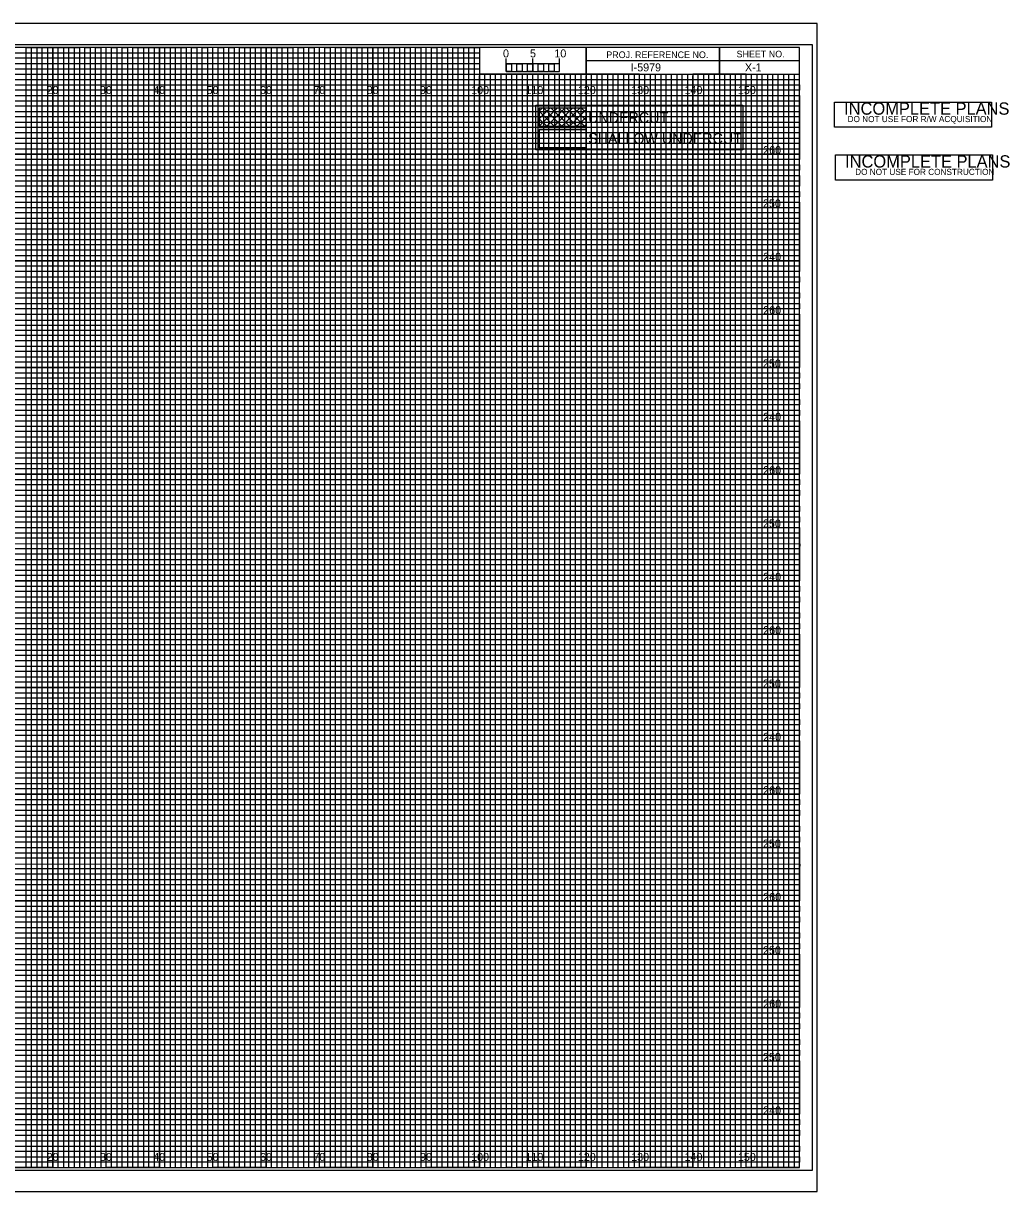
# Model space of a CAD drawing. Extents: x -13 to 359, y -5 to 2854.
# Drawn here: x 174.5 to 359.4, y -4.5 to 214.5 of the extents above; entities that cross this region are included whole.
import ezdxf

# ---------------------------------------------------------------- set-up
doc = ezdxf.new("R2010")
doc.units = 0
for name, color, linetype in [('Exist CMT Pavement', 7, 'Continuous'), ('Exist Cross Section Cell', 7, 'Continuous'), ('Exist XS Ground Line', 7, 'Continuous'), ('Prop CMT Conc Surface', 7, 'Continuous'), ('Prop CMT Concrete Structures', 7, 'Continuous'), ('Prop CMT DNC', 7, 'Continuous'), ('Prop CMT Guardrail Graphics', 7, 'Continuous'), ('Prop CMT Pvmt Course 1', 7, 'Continuous'), ('Prop CMT Pvmt Course 1 CG', 7, 'Continuous'), ('Prop CMT Pvmt Course 1 Wedge', 7, 'Continuous'), ('Prop CMT Pvmt Course 2', 7, 'Continuous'), ('Prop CMT Pvmt Course 2 Wedge', 7, 'Continuous'), ('Prop CMT Pvmt Surface', 7, 'Continuous'), ('Prop CMT Shear Line', 7, 'Continuous'), ('Prop CMT Shld Paved Course 1', 7, 'Continuous'), ('Prop CMT Shld Paved Course 2', 7, 'Continuous'), ('Prop CMT Shld Paved Course 3', 7, 'Continuous'), ('Prop CMT Slope Grass', 7, 'Continuous'), ('Prop CMT Subgrade Earthwork', 7, 'Continuous'), ('Scratch_Level_0', 7, 'Continuous')]:
    doc.layers.add(name, color=color, linetype=linetype)

msp = doc.modelspace()

# ---------------------------------------------------------------- linework, layer by layer
at = {"layer": 'Exist XS Ground Line'}
for p, q in [((190, 210), (180, 210)), ((180, 210), (180, 0)), ((190, 0), (190, 210)), ((210, 210), (200, 210)), ((200, 210), (200, 0)), ((210, 0), (210, 210)), ((230, 210), (220, 210)), ((220, 210), (220, 0)), ((230, 0), (230, 210)), ((250, 210), (240, 210)), ((240, 210), (240, 0)), ((250, 0), (250, 210)), ((260, 210), (260, 0)), ((270, 0), (270, 205)), ((290, 205), (280, 205)), ((280, 205), (280, 0)), ((290, 0), (290, 205)), ((310, 205), (300, 205)), ((300, 205), (300, 0)), ((310, 0), (310, 205)), ((180, 0), (170, 0)), ((200, 0), (190, 0)), ((220, 0), (210, 0)), ((240, 0), (230, 0)), ((260, 0), (250, 0)), ((280, 0), (270, 0)), ((300, 0), (290, 0)), ((320, 0), (310, 0)), ((320, 0), (320, 0))]:
    msp.add_line(p, q, dxfattribs=at)
for points in [[(0, 200), (320, 200), (320, 190), (0, 190)], [(0, 180), (320, 180), (320, 170), (0, 170)], [(0, 160), (320, 160), (320, 150), (0, 150)], [(0, 140), (320, 140), (320, 130), (0, 130)], [(0, 120), (320, 120), (320, 110), (0, 110)], [(0, 100), (320, 100), (320, 90), (0, 90)], [(0, 80), (320, 80), (320, 70), (0, 70)], [(0, 60), (320, 60), (320, 50), (0, 50)], [(0, 40), (320, 40), (320, 30), (0, 30)], [(0, 20), (320, 20), (320, 10), (0, 10)]]:
    msp.add_lwpolyline(points, dxfattribs=at)
at = {"layer": 'Prop CMT Conc Surface'}
for p, q in [((265, 205.49), (265, 207.9)), ((265, 206.9), (265, 207.9)), ((270, 205.49), (270, 207.9)), ((275, 205.49), (275, 207.9)), ((275, 206.9), (275, 207.9))]:
    msp.add_line(p, q, dxfattribs=at)
for points in [[(275, 206.9), (265, 206.9), (265, 205.49), (275, 205.49)], [(265, 206.9), (266, 206.9), (266, 205.49), (265, 205.49)], [(267, 206.9), (268, 206.9), (268, 205.49), (267, 205.49)], [(269, 206.9), (270, 206.9), (270, 205.49), (269, 205.49)], [(271, 206.9), (272, 206.9), (272, 205.49), (271, 205.49)], [(273, 206.9), (274, 206.9), (274, 205.49), (273, 205.49)]]:
    msp.add_lwpolyline(points, close=True, dxfattribs=at)
at = {"layer": 'Prop CMT Concrete Structures'}
for p, q in [((305, 210), (305, 205)), ((305, 205), (305, 210)), ((280, 207.5), (280, 205)), ((320, 207.49), (280, 207.49)), ((280, 205), (320, 205))]:
    msp.add_line(p, q, dxfattribs=at)
for points in [[(320, 210), (0, 210), (0, 0), (320, 0)], [(280, 210), (260, 210), (260, 205.03), (280, 205.03)], [(320, 210), (280, 210), (280, 205), (320, 205)]]:
    msp.add_lwpolyline(points, close=True, dxfattribs=at)
at = {"layer": 'Prop CMT DNC'}
for p, q in [((323.3, 214.5), (-13.4, 214.5)), ((-13.4, -4.5), (323.3, -4.5))]:
    msp.add_line(p, q, dxfattribs=at)
at = {"layer": 'Prop CMT Guardrail Graphics'}
msp.add_lwpolyline([(270.59, 199.19), (309.38, 199.19), (309.38, 190.78), (270.59, 190.78)], close=True, dxfattribs=at)
at = {"layer": 'Prop CMT Pvmt Course 1'}
for p, q in [((0, 209), (260, 209)), ((260, 209), (260, 207.98)), ((260, 207.98), (0, 207.98)), ((0, 207), (260, 207)), ((260, 205.89), (0, 205.89)), ((260, 207), (260, 205.89)), ((0, 204), (320, 204))]:
    msp.add_line(p, q, dxfattribs=at)
for points in [[(0, 203), (270, 203), (320, 203), (320, 202), (0, 202)], [(0, 201), (320, 201), (320, 199), (0, 199)], [(0, 198), (320, 198), (320, 197), (0, 196.98)], [(0, 196), (320, 196), (320, 194), (0, 194)], [(0, 193), (320, 193), (320, 192), (0, 192)], [(0, 191), (320, 191), (320, 189), (0, 189)], [(0, 188), (320, 188), (320, 187), (0, 187)], [(0, 186), (320, 186), (320, 184), (0, 184)], [(0, 183), (320, 183), (320, 182), (0, 182)], [(0, 181), (320, 181), (320, 179), (0, 179)], [(0, 178), (320, 178), (320, 177), (0, 177)], [(0, 176), (320, 176), (320, 173.95), (320, 173), (320, 172), (0, 172)], [(0, 174), (320, 174), (320, 173), (0, 173)], [(0, 171), (320, 171), (320, 169), (0, 169.03)], [(0, 169.03), (320, 169), (320, 168), (0, 168)], [(0, 167), (320, 167), (320, 166), (0, 166)], [(0, 164), (320, 164), (320, 163), (0, 163)], [(0, 162), (320, 162), (320, 161), (0, 161)], [(-0.07, 158.89), (320, 158.89), (320, 157.88), (-0.07, 157.88)], [(0, 157), (320, 157), (320, 156), (0, 156)], [(0, 154), (320, 154), (320, 153), (0, 153)], [(0, 152), (320, 152), (320, 151), (0, 151)], [(0, 149), (320, 149), (320, 148), (0, 148)], [(0, 147), (320, 147), (320, 146), (0, 146)], [(0, 144), (320, 144), (320, 143), (0, 143)], [(0, 142), (320, 142), (320, 141), (0, 141)], [(0, 139), (320, 139), (319.99, 137.98), (0, 138)], [(0, 137), (320, 137), (320, 136), (0, 136)], [(0, 134), (320, 134), (320, 133), (0, 133)], [(0, 132), (320, 132), (320, 131), (0, 131)], [(0, 129), (320, 129), (320, 128), (0, 128)], [(0, 127), (320, 127), (320, 126), (0, 126)], [(0, 124), (320, 124), (320, 123), (0, 123)], [(0, 122), (320, 122), (320, 121), (0, 121)], [(0, 119), (320, 119), (320, 118), (0, 118)], [(0, 116.99), (320.07, 116.91), (320, 116), (0, 116)], [(0, 114), (320, 114), (320, 113), (0, 113)], [(0, 112), (320, 112), (320, 111), (0, 111)], [(0, 109), (320, 109), (320, 108), (0, 108)], [(0, 107), (320, 107), (320, 106), (0, 106)], [(0, 104), (320, 104), (320, 103), (0, 103)], [(0, 102), (320, 102), (320, 101), (0, 101)], [(0, 99), (320, 99), (320, 98), (0, 98)], [(0, 97), (320, 97), (320, 96), (0, 96)], [(0, 94), (320, 94), (320, 93), (0, 93)], [(0, 92), (320, 92), (320, 91), (0, 91)], [(0, 89), (320, 89), (320, 88), (0, 88)], [(0, 87), (320, 87), (320, 86), (0, 86)], [(0, 84), (320, 84), (320, 83), (0, 83)], [(0, 82), (320, 82), (320, 81), (0, 81)], [(0, 79), (320, 79), (319.99, 77.98), (0, 78)], [(0, 77), (320, 77), (320, 76), (0, 76)], [(0, 74), (320, 74), (320, 73), (0, 73)], [(0, 72), (320, 72), (320, 71), (0, 71)], [(0, 69), (320, 69), (320, 68), (0, 68)], [(0, 67), (320, 67), (320, 66), (0, 66)], [(0, 64), (320, 64), (320, 63), (0, 63)], [(0, 62), (320, 62), (320, 61), (0, 61)], [(0, 59), (320, 59), (320, 58), (0, 58)], [(0, 56.99), (320.07, 56.91), (320, 56), (0, 56)], [(0, 54), (320, 54), (320, 53), (0, 53)], [(0, 52), (320, 52), (320, 51), (0, 51)], [(0, 49), (320, 49), (320, 48), (0, 48)], [(0, 47), (320, 47), (320, 46), (0, 46)], [(0, 44), (320, 44), (320, 43), (0, 43)], [(0, 42), (320, 42), (320, 41), (0, 41)], [(0, 39), (320, 39), (320, 38), (0, 38)], [(0, 37), (320, 37), (320, 36), (0, 36)], [(0, 34), (320, 34), (320, 33), (0, 33)], [(0, 32), (320, 32), (320, 31), (0, 31)], [(0, 29), (320, 29), (320, 28), (0, 28)], [(0, 27), (320, 27), (320, 26), (0, 26)], [(0, 24), (320, 24), (320, 23), (0, 23)], [(0, 22), (320, 22), (320, 21), (0, 21)], [(0, 19), (320, 19), (320, 18), (0, 18)], [(0, 17), (320, 17), (320, 16), (0, 16)], [(0, 14), (320, 14), (320, 13), (0, 13)], [(0, 12), (320, 12), (320, 11), (0, 11)], [(0, 9), (320, 9), (320, 8), (0, 8)], [(0, 7), (320, 7), (320, 6), (0, 6)], [(0, 4), (320, 4), (320, 3), (0, 3)], [(0, 2), (320, 2), (320, 1), (0, 1)]]:
    msp.add_lwpolyline(points, dxfattribs=at)
at = {"layer": 'Prop CMT Pvmt Course 1 CG'}
for p, q in [((267, 205), (266.01, 205)), ((266.01, 205), (266.01, 0)), ((267, 0), (267, 205)), ((269, 205), (268, 205)), ((268, 205), (268, 0)), ((269, 0), (269, 205)), ((266.01, 0), (265, 0)), ((268, 0), (267, 0))]:
    msp.add_line(p, q, dxfattribs=at)
for points in [[(175, 0), (176, 0), (176, 210), (177, 210), (177, 0)], [(177, 0), (178, 0), (178, 210), (179, 210), (179, 0)], [(180, 0), (181, 0), (181, 210), (182, 210), (182, 0)], [(182, 0), (183, 0), (183, 210), (184, 210), (184, 0)], [(185, 0), (186, 0), (186, 210), (187, 210), (187, 0)], [(187, 0), (188, 0), (188, 210), (189, 210), (189, 0)], [(190, 0), (191, 0), (191, 210), (192, 210), (192, 0)], [(192, 0), (193, 0), (193, 210), (194, 210), (194, 0)], [(195, 0), (196, 0), (196, 210), (197, 210), (197, 0)], [(197, 0), (198, 0), (198, 210), (199, 210), (199, 0)], [(200, 0), (201, 0), (201, 210), (202, 210), (202, 0)], [(202, 0), (203, 0), (203, 210), (204, 210), (204, 0)], [(205, 0), (206, 0), (206, 210), (207, 210), (207, 0)], [(207, 0), (208, 0), (208, 210), (209, 210), (209, 0)], [(210, 0), (211, 0), (211, 210), (212, 210), (212, 0)], [(212, 0), (213, 0), (213, 210), (214, 210), (214, 0)], [(215, 0), (216, 0), (216, 210), (217, 210), (217, 0)], [(217, 0), (218, 0), (218, 210), (219, 210), (219, 0)], [(220, 0), (221, 0), (221, 210), (222, 210), (222, 0)], [(222, 0), (223, 0), (223, 210), (224, 210), (224, 0)], [(225, 0), (226, 0), (226, 210), (227, 210), (227, 0)], [(227, 0), (228, 0), (228, 210), (229, 210), (229, 0)], [(230, 0), (231, 0), (231, 210), (232, 210), (232, 0)], [(232, 0), (233, 0), (233, 210), (234, 210), (234, 0)], [(235, 0), (236, 0), (236, 210), (237, 210), (237, 0)], [(237, 0), (238, 0), (238, 210), (239, 210), (239, 0)], [(240, 0), (241, 0), (241, 210), (242, 210), (242, 0)], [(242, 0), (243, 0), (243, 210), (244, 210), (244, 0)], [(245, 0), (246, 0), (246, 210), (247, 210), (247, 0)], [(247, 0), (248, 0), (248, 210), (249, 210), (249, 0)], [(250, 0), (251, 0), (251, 210), (252, 210), (252, 0)], [(252, 0), (253, 0), (253, 210), (254, 210), (254, 0)], [(255, 0), (256, 0), (256, 210), (257, 210), (257, 0)], [(257, 0), (258, 0), (258, 210), (259, 210), (259, 0)], [(260, 0), (261, 0), (261, 205), (262.02, 205), (262.02, 0)], [(262, 0), (263, 0), (263, 205), (263.99, 205), (263.99, 0)], [(270, 0), (270.98, 0), (270.98, 205), (272, 205), (272, 0)], [(272, 0), (273, 0), (273, 205), (274.05, 205), (274.05, 0)], [(275, 0), (276, 0), (276, 205), (277, 205), (277, 0)], [(277, 0), (278, 0), (278, 205), (279, 205), (279, 0)], [(280, 0), (281, 0), (281, 205), (282, 205), (282, 0)], [(282, 0), (283, 0), (283, 205), (284, 205), (284, 0)], [(285, 0), (286, 0), (286, 205), (287, 205), (287, 0)], [(287, 0), (288, 0), (288, 205), (289, 205), (289, 0)], [(290, 0), (291, 0), (291, 205), (292, 205), (292, 0)], [(292, 0), (293, 0), (293, 205), (294, 205), (294, 0)], [(295, 0), (296, 0), (296, 205), (297, 205), (297, 0)], [(297, 0), (298, 0), (298, 205), (299, 205), (299, 0)], [(300, 0), (301, 0), (301, 205), (302, 205), (302, 0)], [(302, 0), (303, 0), (303, 205), (304, 205), (304, 0)], [(305, 0), (306, 0), (306, 205), (307, 205), (307, 0)], [(307, 0), (308, 0), (308, 205), (309, 205), (309, 0)], [(310, 0), (311, 0), (311, 205), (312, 205), (312, 0)], [(312, 0), (313, 0), (313, 205), (314, 205), (314, 0)], [(315, 0), (316, 0), (316, 205), (317, 205), (317, 0)], [(317, 0), (318, 0), (318, 205), (319, 205), (319, 0)]]:
    msp.add_lwpolyline(points, dxfattribs=at)
at = {"layer": 'Prop CMT Pvmt Surface'}
for points in [[(326.56, 195.04), (326.56, 199.74), (355.96, 199.74), (355.96, 195.04)], [(326.74, 185.13), (326.74, 189.83), (356.14, 189.83), (356.14, 185.13)]]:
    msp.add_lwpolyline(points, close=True, dxfattribs=at)
at = {"layer": 'Prop CMT Shear Line'}
for p, q in [((180, 0), (180, 210)), ((190, 0), (190, 210)), ((200, 0), (200, 210)), ((210, 0), (210, 210)), ((220, 0), (220, 210)), ((230, 0), (230, 210)), ((240, 0), (240, 210)), ((250, 0), (250, 210)), ((260, 0), (260, 204.69)), ((270, 0), (270, 204.69)), ((280, 0), (280, 204.69)), ((290, 0), (290, 204.69)), ((300, 0), (300, 204.69)), ((310, 0), (310, 204.69)), ((0, 200), (320, 200)), ((0, 190), (320, 190)), ((0, 180), (320, 180)), ((0, 170), (320, 170)), ((0, 160), (320, 160)), ((0, 150), (320, 150)), ((0, 140), (320, 140)), ((0, 130), (320, 130)), ((0, 120), (320, 120)), ((0, 110), (320, 110)), ((0, 100), (320, 100)), ((0, 90), (320, 90)), ((0, 80), (320, 80)), ((0, 70), (320, 70)), ((0, 60), (320, 60)), ((0, 50), (320, 50)), ((0, 40), (320, 40)), ((0, 30), (320, 30)), ((0, 20), (320, 20)), ((0, 10), (320, 10))]:
    msp.add_line(p, q, dxfattribs=at)
at = {"layer": 'Prop CMT Shld Paved Course 1'}
msp.add_lwpolyline([(271.19, 194.58), (279.99, 194.58), (279.99, 191.19), (271.19, 191.19)], close=True, dxfattribs=at)
at = {"layer": 'Prop CMT Shld Paved Course 2'}
msp.add_lwpolyline([(271.19, 191.19), (279.99, 191.19), (279.99, 194.58), (271.19, 194.58)], close=True, dxfattribs=at)
at = {"layer": 'Prop CMT Shld Paved Course 3'}
for p, q in [((271.19, 195.2), (274.59, 198.6)), ((271.19, 196.62), (273.17, 198.6)), ((271.19, 198.03), (271.76, 198.6)), ((271.19, 198.03), (274.02, 195.2)), ((272.04, 198.6), (275.44, 195.2)), ((272.61, 195.2), (276, 198.6)), ((273.46, 198.6), (276.85, 195.2)), ((274.02, 195.2), (277.42, 198.6)), ((274.87, 198.6), (278.27, 195.2)), ((275.44, 195.2), (278.83, 198.6)), ((276.29, 198.6), (279.68, 195.2)), ((276.85, 195.2), (279.99, 198.34)), ((277.7, 198.6), (279.99, 196.31)), ((279.12, 198.6), (279.99, 197.72)), ((271.19, 196.62), (272.61, 195.2)), ((278.27, 195.2), (279.99, 196.93)), ((279.68, 195.2), (279.99, 195.52))]:
    msp.add_line(p, q, dxfattribs=at)
msp.add_lwpolyline([(271.19, 195.2), (279.99, 195.2), (279.99, 198.6), (271.19, 198.6)], close=True, dxfattribs=at)
at = {"layer": 'Prop CMT Slope Grass'}
msp.add_lwpolyline([(-10.8, -0.5), (322.4, -0.5), (322.4, 210.5), (-10.8, 210.5)], close=True, dxfattribs=at)
at = {"layer": 'Prop CMT Subgrade Earthwork'}
msp.add_lwpolyline([(-13.4, -4.5), (323.3, -4.5), (323.3, 214.5), (-13.4, 214.5)], close=True, dxfattribs=at)
at = {"layer": 'Scratch_Level_0'}
for points in [[(165, 0), (175, 0), (175, 210), (185, 210), (185, 0), (195, 0), (195, 210), (205, 210), (205, 0), (215, 0), (215, 210), (225, 210), (225, 0), (235, 0), (235, 210), (245, 210), (245, 0), (255, 0), (255, 210), (259.93, 210), (260, 210), (260, 205), (264.99, 205), (264.99, 0), (275, 0), (275, 205), (285, 205), (285, 0), (295, 0), (295, 205), (305, 205), (305, 0), (315, 0), (315, 205)], [(0, 205), (275, 205)], [(0, 185), (320, 185), (320, 195), (0, 195)], [(0, 165), (320, 165), (320, 175), (0, 175)], [(0, 145), (320, 145), (320, 155), (0, 155)], [(0, 125), (320, 125), (320, 135), (0, 135)], [(0, 105), (320, 105), (320, 115), (0, 115)], [(0, 85), (320, 85), (320, 95), (0, 95)], [(0, 65), (320, 65), (320, 75), (0, 75)], [(0, 45), (320, 45), (320, 55), (0, 55)], [(0, 25), (320, 25), (320, 35), (0, 35)], [(0, 5), (320, 5), (320, 15), (0, 15)]]:
    msp.add_lwpolyline(points, dxfattribs=at)

# ---------------------------------------------------------------- texts
at = {"layer": 'Exist CMT Pavement'}
for s, p in [('5', (269.47, 208.12)), ('10', (274.04, 208.12))]:
    msp.add_text(s, height=1.5, dxfattribs=at).set_placement(p)
at = {"layer": 'Exist Cross Section Cell'}
for s, p in [('20', (178.86, 201.25)), ('30', (188.86, 201.25)), ('40', (198.86, 201.25)), ('50', (208.86, 201.25)), ('60', (218.86, 201.25)), ('70', (228.86, 201.25)), ('80', (238.86, 201.25)), ('90', (248.86, 201.25)), ('100', (258.44, 201.25)), ('110', (268.62, 201.25)), ('120', (278.44, 201.25)), ('130', (288.44, 201.25)), ('140', (298.44, 201.25)), ('150', (308.44, 201.25)), ('20', (178.86, 1.25)), ('30', (188.86, 1.25)), ('40', (198.86, 1.25)), ('50', (208.86, 1.25)), ('60', (218.86, 1.25)), ('70', (228.86, 1.25)), ('80', (238.86, 1.25)), ('90', (248.86, 1.25)), ('100', (258.44, 1.25)), ('110', (268.62, 1.25)), ('120', (278.44, 1.25)), ('130', (288.44, 1.25)), ('140', (298.44, 1.25)), ('150', (308.44, 1.25))]:
    msp.add_text(s, height=1.5, dxfattribs=at).set_placement(p)
at = {"layer": 'Prop CMT Conc Surface'}
msp.add_text('0', height=1.5, dxfattribs=at).set_placement((264.41, 208.12))
at = {"layer": 'Prop CMT Concrete Structures'}
for s, p in [('PROJ. REFERENCE NO.', (283.77, 207.99)), ('SHEET NO.', (308.19, 208.12))]:
    msp.add_text(s, height=1.25, dxfattribs=at).set_placement(p)
at = {"layer": 'Prop CMT Pvmt Course 1 Wedge'}
msp.add_text('X-1', height=1.5, dxfattribs=at).set_placement((309.76, 205.5))
at = {"layer": 'Prop CMT Pvmt Course 2'}
for s, p in [('260', (313.19, 190)), ('250', (313.15, 180)), ('240', (313.19, 170)), ('260', (313.19, 160)), ('250', (313.15, 150)), ('240', (313.19, 140)), ('260', (313.19, 130)), ('250', (313.15, 120)), ('240', (313.19, 110)), ('260', (313.19, 100)), ('250', (313.15, 90)), ('240', (313.19, 80)), ('260', (313.19, 70)), ('250', (313.15, 60)), ('260', (313.19, 50)), ('250', (313.15, 40)), ('260', (313.19, 30)), ('250', (313.15, 20)), ('240', (313.19, 10))]:
    msp.add_text(s, height=1.5, dxfattribs=at).set_placement(p)
at = {"layer": 'Prop CMT Pvmt Course 2 Wedge'}
msp.add_text('I-5979', height=1.5, dxfattribs=at).set_placement((288.34, 205.5))
at = {"layer": 'Prop CMT Pvmt Surface'}
for s, height, p in [('INCOMPLETE PLANS', 2.304, (328.35, 197.38)), ('DO NOT USE FOR R/W ACQUISITION', 1.152, (329, 195.99)), ('INCOMPLETE PLANS', 2.304, (328.53, 187.47)), ('DO NOT USE FOR CONSTRUCTION', 1.152, (330.42, 186.08))]:
    msp.add_text(s, height=height, dxfattribs=at).set_placement(p)
at = {"layer": 'Prop CMT Shld Paved Course 3'}
for s, p in [('UNDERCUT', (280.37, 195.83)), ('SHALLOW UNDERCUT', (280.37, 191.93))]:
    msp.add_text(s, height=2, dxfattribs=at).set_placement(p)

doc.saveas('drawing.dxf')
